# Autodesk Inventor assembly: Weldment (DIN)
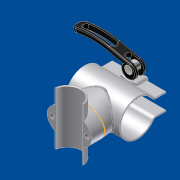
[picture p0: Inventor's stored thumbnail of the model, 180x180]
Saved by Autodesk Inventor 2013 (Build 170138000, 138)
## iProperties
Length Units: 11269
Angle Units: 11283
Time Units: 11279
Mass Units: 11290
Length Display Precision: 3
Angle Display Precision: 2
Part Number: Weldment (DIN)
Document SubType Name: Weldment
Created: 2002-06
Designer: smithga
Part Number: Clamp_welded
Created: 2002-10
Designer: roithn
Control State: 0
Master: False
Shininess: 64.0
Angle Units: 11279
Time Units: 11290
Mass Units: 11283
Compacted: True
Density: 0.0
Volumn: 0.0
Area: 0.0
PropertySet Name: Model Information
Author: roithn
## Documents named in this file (7)
- C:\Webworld\Webworld2014\ATC2013\Assemblies\ATC-Baby Carriage\CLAMPDAMPER\Clamp_welded.iam
- C:\Webworld\Webworld2014\ATC2013\Assemblies\ATC-Baby Carriage\CLAMPDAMPER\Clamp_A.ipt
- C:\Webworld\Webworld2014\ATC2013\Assemblies\ATC-Baby Carriage\CLAMPDAMPER\Clamp_B.ipt
- C:\Webworld\Webworld2014\ATC2013\Assemblies\ATC-Baby Carriage\CLAMPDAMPER\Clamp_C.ipt
- C:\Webworld\Webworld2014\ATC2013\Assemblies\ATC-Baby Carriage\CLAMPDAMPER\Bolt d5mm l18mm.ipt
- C:\Webworld\Webworld2014\ATC2013\Assemblies\ATC-Baby Carriage\CLAMPDAMPER\Rapid_fastener.iam
- C:\ATC - WARREN\warren\NUIG YEAR 3 2008 INVENTOR 2008\Baby Carriage\CLAMPDAMPER\Bolt.ipt
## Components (5 placed, 5 different names)
1. Clamp_A:1 — Flush:1, Flush:2
2. Clamp_B:1 — Flush:1, Flush:2, Mate:1
3. Clamp_C:1 — Flush:3, Mate:1, Angle:1, Angle:2
4. Rapid_fastener:1 [sub-assembly] — Angle:2
5. Bolt d5mm l18mm:1
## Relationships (6: Flush 3, Angle 2, Mate 1)
- Flush:1: Clamp_A:1 ↔ Clamp_B:1
- Flush:2: Clamp_A:1 ↔ Clamp_B:1
- Flush:3: Clamp_C:1
- Mate:1: Clamp_B:1 ↔ Clamp_C:1
- Angle:1: Clamp_C:1
- Angle:2: Clamp_C:1 ↔ Rapid_fastener:1
